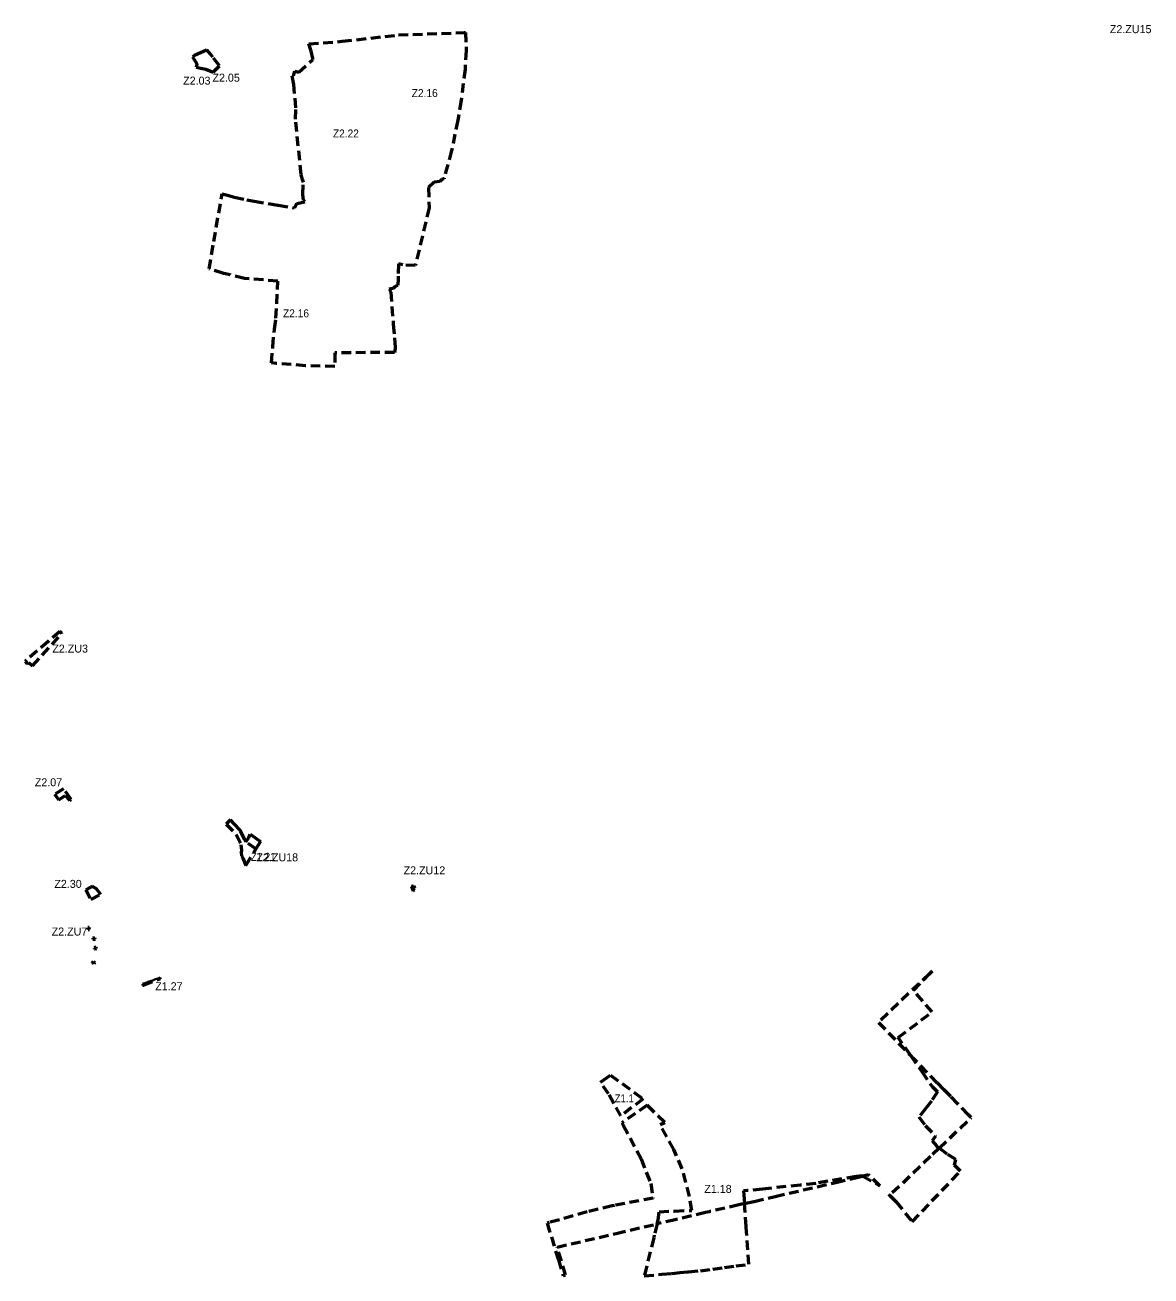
# Model space of a CAD drawing. Extents: x -650368 to -643203, y -1074215 to -1066658.
# Drawn here: x -646160 to -643203, y -1073629 to -1070346 of the extents above; entities that cross this region are included whole.
import ezdxf
from ezdxf.enums import TextEntityAlignment as Align

# ---------------------------------------------------------------- set-up
doc = ezdxf.new("R2010")
doc.units = 0
doc.header["$LTSCALE"] = 8.4
doc.header["$PDMODE"] = 32
doc.header["$PDSIZE"] = 4.2
doc.linetypes.add('MEDIUM_DASHED', pattern=[4.5, 3, -1.5])
for name, color, linetype, lineweight in [('57', 7, 'MEDIUM_DASHED', 40), ('58', 7, 'MEDIUM_DASHED', 53), ('59', 7, 'MEDIUM_DASHED', 53)]:
    doc.layers.add(name, color=color, linetype=linetype, lineweight=lineweight)
for name, color, linetype in [('60', 7, 'Continuous'), ('61', 7, 'Continuous'), ('62', 7, 'Continuous')]:
    doc.layers.add(name, color=color, linetype=linetype)

msp = doc.modelspace()

# ---------------------------------------------------------------- linework, layer by layer
at = {"layer": '57', "lineweight": 53}
msp.add_line((-643888.98, -1073417.72), (-643888.981, -1073417.721), dxfattribs=at)
for points in [[(-645568.38, -1072469.68), (-645550.485, -1072482.397), (-645541.56, -1072488.74), (-645553.35, -1072508.1), (-645579.92, -1072489.22), (-645572.13, -1072477.78)], [(-643834.374, -1073049.804), (-643866.47, -1073003.5), (-643777.24, -1072936.14), (-643826.71, -1072879.74), (-643785.54, -1072837.18), (-643782.4, -1072833.93), (-643779.11, -1072830.53), (-643777.25, -1072828.61), (-643779.2, -1072830.47), (-643782.64, -1072833.75), (-643784.73, -1072835.75), (-643918.49, -1072963.57)], [(-643795.55, -1073233.88), (-643768.54, -1073261.84), (-643777.32, -1073274.48), (-643765.72, -1073287.79), (-643758.684, -1073293.221), (-643674.98, -1073213.24), (-643682, -1073206.04), (-643710.23, -1073177.1), (-643728.75, -1073158.08), (-643746.24, -1073140.18), (-643764.26, -1073121.7), (-643827.17, -1073057.19), (-643834.374, -1073049.804), (-643804.87, -1073092.37), (-643776.95, -1073132.64), (-643763.84, -1073145.39), (-643779.56, -1073170.18), (-643793.58, -1073187.74), (-643812.17, -1073211.03)], [(-644648.95, -1073120.47), (-644630.58, -1073107.78), (-644622.03, -1073101.88), (-644536.62, -1073164.33), (-644595.18, -1073208.98), (-644627.53, -1073151.26)], [(-644516.53, -1073386.51), (-644510.31, -1073424.47), (-644611.64, -1073443.78), (-644618.16, -1073445.33), (-644683.75, -1073460.89), (-644783.15, -1073488.75), (-644785.53, -1073489.54), (-644788.93, -1073490.66), (-644758.76, -1073587.1), (-644746.45, -1073628.1), (-644743.07, -1073627.19), (-644740.13, -1073626.4), (-644762.37, -1073553.42), (-644607.27, -1073517.36), (-644499.826, -1073492.38), (-644497.21, -1073481.81), (-644494.43, -1073460.27), (-644453.73, -1073458.62), (-644408.96, -1073456.81), (-644414.5, -1073420.03), (-644433.72, -1073348.21), (-644455.52, -1073296.92), (-644492.22, -1073231.83), (-644479.79, -1073226.24), (-644523.53, -1073183.36), (-644526.14, -1073180.8), (-644592.38, -1073226.73), (-644588.63, -1073233.63), (-644542.1, -1073321.83)], [(-644270.711, -1073439.156), (-644244.95, -1073433.17), (-644189.82, -1073420.36), (-644030.68, -1073383.37), (-643971.48, -1073369.61), (-643959.207, -1073366.76), (-643960.86, -1073365.8), (-643977.03, -1073367.56), (-644083.16, -1073386.16), (-644123.78, -1073390.8), (-644223.23, -1073400.92), (-644262.05, -1073404.87), (-644273.19, -1073406), (-644272.42, -1073416.33)], [(-643914.7, -1073392.62), (-643944.57, -1073363.36), (-643951.41, -1073364.95), (-643959.207, -1073366.76)], [(-644533.65, -1073629.06), (-644487.21, -1073624.67), (-644460.51, -1073622.14), (-644438.98, -1073620.1), (-644420.09, -1073618.31), (-644417.5, -1073618.08), (-644385.91, -1073615.23), (-644353.71, -1073610.96), (-644323.09, -1073606.89), (-644292.41, -1073602.82), (-644258.55, -1073598.32), (-644266, -1073502.03), (-644266.16, -1073499.93), (-644270.711, -1073439.156), (-644285.06, -1073442.49), (-644360.33, -1073459.98), (-644363.26, -1073460.66), (-644372.58, -1073462.83), (-644452.17, -1073481.3), (-644499.826, -1073492.38), (-644507.17, -1073522.06), (-644508.85, -1073528.86)]]:
    msp.add_lwpolyline(points, close=True, dxfattribs=at)
at = {"layer": '57'}
for points in [[(-645834.208, -1072856.314), (-645837.027, -1072857.313), (-645839.908, -1072858.343), (-645842.74, -1072859.344), (-645845.619, -1072860.364), (-645848.628, -1072861.433), (-645851.48, -1072862.586), (-645850.187, -1072866.251), (-645850.17, -1072866.3), (-645849.705, -1072867.618), (-645849.703, -1072867.622)], [(-645849.703, -1072867.622), (-645848.52, -1072867.16), (-645803.84, -1072849.72), (-645805.159, -1072845.994)], [(-645805.159, -1072845.994), (-645808.177, -1072847.063), (-645811.148, -1072848.124), (-645813.978, -1072849.124), (-645816.948, -1072850.184), (-645819.779, -1072851.184), (-645822.726, -1072852.233), (-645825.527, -1072853.233), (-645828.409, -1072854.254), (-645834.208, -1072856.314)]]:
    msp.add_lwpolyline(points, dxfattribs=at)
at = {"layer": '57', "lineweight": 53}
msp.add_lwpolyline([(-643888.981, -1073417.721), (-643871.9, -1073434.39), (-643830.32, -1073486.65), (-643702.83, -1073354.29), (-643718.36, -1073338.15), (-643715.05, -1073323.24), (-643738.06, -1073309.14), (-643758.684, -1073293.221), (-643781.98, -1073315.48), (-643888.98, -1073417.72)], dxfattribs=at)
at = {"layer": '57'}
msp.add_point((-643888.98, -1073417.72), dxfattribs=at)
at = {"layer": '58'}
for points in [[(-645642.52, -1070788.7), (-645625, -1070793.5), (-645610.25, -1070797.55), (-645577.54, -1070804.13), (-645558.3, -1070808), (-645494.82, -1070818.45), (-645494.82, -1070818.45), (-645452.31, -1070825.52), (-645445.81, -1070814.06), (-645424.969, -1070809.563), (-645428.39, -1070806.09), (-645430, -1070790.68), (-645428.73, -1070758.67), (-645430.84, -1070751.43), (-645434.53, -1070738.77), (-645449.82, -1070592.72), (-645448.36, -1070563), (-645454.02, -1070501.52), (-645458.46, -1070478.86), (-645455.09, -1070479.21), (-645451.226, -1070466.394), (-645440.61, -1070469.53), (-645404.4, -1070435.88), (-645404.34, -1070433.93), (-645408.66, -1070414.62), (-645409.38, -1070411.41), (-645414.65, -1070395.37), (-645326.62, -1070388.32), (-645179.26, -1070371.74), (-645006.86, -1070365.38), (-645003.03, -1070365.427), (-645001.312, -1070412.099), (-645004.327, -1070461.264), (-645014.277, -1070543.11), (-645023.048, -1070595.033), (-645039.574, -1070675.065), (-645059.308, -1070747.712), (-645059.308, -1070747.712), (-645059.421, -1070749.039), (-645060.538, -1070749.039), (-645065.17, -1070751.39), (-645070.3, -1070755.92), (-645085.58, -1070758.04), (-645100.268, -1070771.946), (-645098.438, -1070825.558), (-645134.973, -1070977.077), (-645167.47, -1070975.2), (-645178.73, -1070972.35), (-645179.87, -1071004.67), (-645180.13, -1071012.09), (-645180.72, -1071028.86), (-645186.18, -1071030.83), (-645188.39, -1071032.86), (-645193.24, -1071037.31), (-645203.66, -1071038.81), (-645199.57, -1071046.58), (-645192.68, -1071130.95), (-645189.75, -1071166.82), (-645187.72, -1071191.68), (-645187.466, -1071194.782), (-645189.902, -1071204.885), (-645346.31, -1071206.07), (-645346.31, -1071206.07), (-645346.67, -1071242.07), (-645423.08, -1071239.85), (-645499.36, -1071233.94)], [(-645499.36, -1071233.94), (-645512.84, -1071231.9), (-645509.22, -1071193.44), (-645509.49, -1071190.38), (-645504.79, -1071144.18), (-645500.94, -1071115.24), (-645495.87, -1071017.81), (-645583.18, -1071010.7), (-645621.05, -1071001.5), (-645637.94, -1070997.4), (-645676.292, -1070985.89), (-645663.99, -1070914.06), (-645642.52, -1070788.7)]]:
    msp.add_lwpolyline(points, dxfattribs=at)
for points in [[(-645665.6, -1070469.04), (-645648.9, -1070452.38), (-645666.99, -1070429.58), (-645672.07, -1070423.18), (-645682.02, -1070410.65), (-645683.52, -1070411.71), (-645699.33, -1070418.25), (-645714.74, -1070425.84), (-645720.48, -1070428.75), (-645715.56, -1070436.27), (-645708.28, -1070447.28), (-645708.42, -1070447.94), (-645710.14, -1070456.31), (-645697.88, -1070458.83), (-645684.78, -1070461.52)], [(-646154, -1072022), (-646150.226, -1072018.826), (-646139.98, -1072027.22), (-646062.91, -1071942.55), (-646068.317, -1071937.555), (-646099.073, -1071963.899), (-646156.858, -1072013.393), (-646160, -1072016)], [(-646071, -1072379.27), (-646054.43, -1072368.34), (-646042.65, -1072381.23), (-646039.16, -1072378.43), (-646058.64, -1072350.29), (-646082.55, -1072364.84)], [(-645620.56, -1072432), (-645632.1, -1072442.93), (-645605.17, -1072470.52), (-645592.9, -1072496.52), (-645591.06, -1072511.06), (-645592.08, -1072517.43), (-645591.03, -1072526.14), (-645588.293, -1072532.287), (-645579.76, -1072551.45), (-645553.35, -1072508.1), (-645579.92, -1072489.22), (-645583.13, -1072482.13), (-645592.91, -1072462.202), (-645594.83, -1072458.48), (-645609.99, -1072443.22)], [(-645140.96, -1072617.82), (-645137.62, -1072616.42), (-645138.54, -1072614.28), (-645139.37, -1072612.36), (-645135.94, -1072611.02), (-645138.46, -1072605.08), (-645141.92, -1072606.43), (-645142.16, -1072605.87), (-645145.23, -1072607.15), (-645141.72, -1072615.2), (-645141.61, -1072615.6)], [(-645995.13, -1072714.74), (-645994.08, -1072719.72), (-645990.99, -1072719.21), (-645991.83, -1072714.17)], [(-645982.09, -1072742.2), (-645981.54, -1072745.4), (-645979.54, -1072744.94), (-645979.29, -1072745.98), (-645975.96, -1072745.2), (-645976.91, -1072741.11)], [(-645978.31, -1072767.48), (-645977.69, -1072770.55), (-645976.22, -1072770.26), (-645972.21, -1072769.44), (-645972.83, -1072766.36), (-645976.84, -1072767.17)], [(-645980.16, -1072803.63), (-645976.62, -1072806.59), (-645978.86, -1072809.21), (-645979.48, -1072809.98), (-645982.99, -1072807.15), (-645982.37, -1072806.37)]]:
    msp.add_lwpolyline(points, close=True, dxfattribs=at)
at = {"layer": '59'}
msp.add_lwpolyline([(-645982.84, -1072606.46), (-645986.86, -1072608.47), (-645986.86, -1072608.47), (-646000.45, -1072615.28), (-645987.44, -1072641.13), (-645960.69, -1072627.73), (-645973.45, -1072611.73)], close=True, dxfattribs=at)

# ---------------------------------------------------------------- texts
at = {"layer": '60', "width": 0.9}
for s, p in [('Z1.21', (-645534.365, -1072539.431)), ('Z1.1', (-644586.089, -1073173.154))]:
    msp.add_text(s, height=21, dxfattribs=at).set_placement(p, align=Align.CENTER)
at = {"layer": '60'}
for s, p in [('Z1.27', (-645782.142, -1072879.024)), ('Z1.18', (-644339.94, -1073410.953))]:
    msp.add_text(s, height=21, dxfattribs=at).set_placement(p, align=Align.CENTER)
at = {"layer": '61'}
for s, p in [('Z2.ZU15', (-643256.13, -1070366.928)), ('Z2.03', (-645708.736, -1070502.139)), ('Z2.05', (-645631.733, -1070494.361)), ('Z2.ZU3', (-646041.486, -1071992.869)), ('Z2.07', (-646098.354, -1072343.68)), ('Z2.ZU18', (-645497.427, -1072540.724)), ('Z2.ZU12', (-645111.005, -1072574.832)), ('Z2.ZU7', (-646043.143, -1072735.475))]:
    msp.add_text(s, height=21, dxfattribs=at).set_placement(p, align=Align.CENTER)
at = {"layer": '61', "width": 0.95}
for s, p in [('Z2.16', (-645110.142, -1070534.756)), ('Z2.22', (-645317.232, -1070640.828)), ('Z2.16', (-645448.24, -1071112.945))]:
    msp.add_text(s, height=21, dxfattribs=at).set_placement(p, align=Align.CENTER)
at = {"layer": '62'}
msp.add_text('Z2.30', height=21, dxfattribs=at).set_placement((-646047.011, -1072610.371), align=Align.CENTER)

doc.saveas('drawing.dxf')
